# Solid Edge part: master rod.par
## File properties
Author: Administrator
Template: normal.par
Last saved by: CADCIM
Revision: 12
Application: Solid Edge
Accuracy: 0.99
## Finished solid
Body 1: solid body, 60 faces, 148 edges, 80 vertices.
  Faces by surface: cylinder 42, plane 18
  Edges by curve: circle 78, line 58, ellipse 12
Bounding box of the edges (mm): 320.500 x 112.000 x 70.000, from (-118.4884, -56, -35) to (202.0116, 56, 35).
Cylindrical faces by radius (mm): R5 x8, R6 x4, R12 x1, R13 x8, R17.5 x1, R26 x1, R31.5 x3, R35 x2, R72.03 x8, R78 x4, R207.0766 x1, R207.2725 x1
Planar faces by outward normal: +y 2, +z 5, -y 2, -z 5, oblique 4
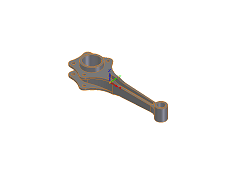
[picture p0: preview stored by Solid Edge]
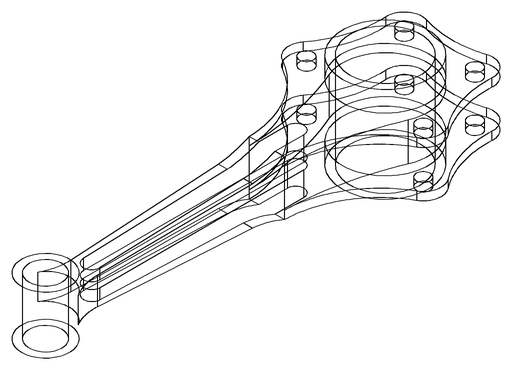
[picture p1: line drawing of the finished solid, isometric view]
